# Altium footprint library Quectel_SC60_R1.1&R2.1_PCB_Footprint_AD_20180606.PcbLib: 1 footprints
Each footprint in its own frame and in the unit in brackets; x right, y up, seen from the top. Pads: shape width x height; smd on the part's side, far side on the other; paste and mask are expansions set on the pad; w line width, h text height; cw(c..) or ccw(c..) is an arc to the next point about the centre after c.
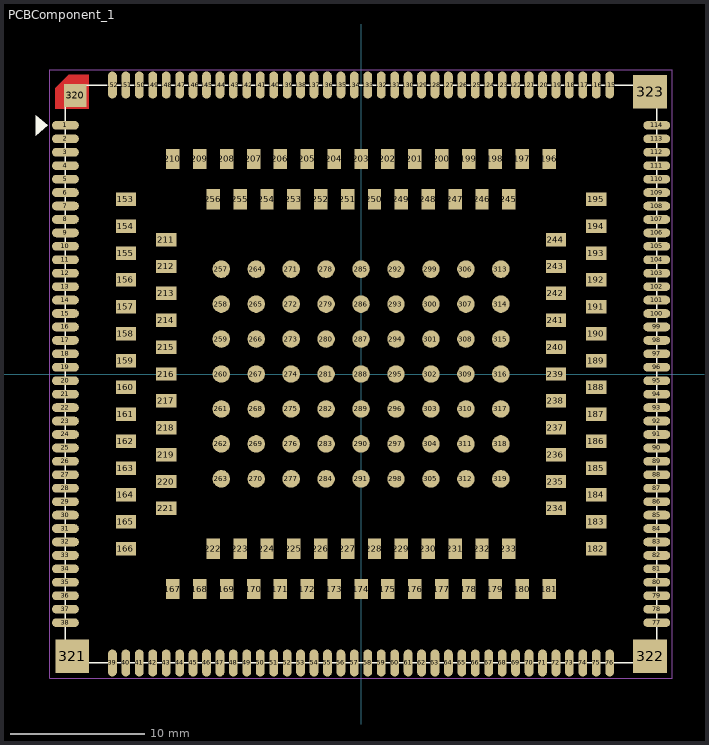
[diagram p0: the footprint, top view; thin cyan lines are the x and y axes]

## PCBComponent_1 [mm]
pads (323):
  oval 2x0.65 smd mask+0.05: 1(-22,18.5) 2(-22,17.5) 3(-22,16.5) 4(-22,15.5) 5(-22,14.5) 6(-22,13.5) 7(-22,12.5) 8(-22,11.5) 9(-22,10.5) 10(-22,9.5) 11(-22,8.5) 12(-22,7.5) 13(-22,6.5) 14(-22,5.5) 15(-22,4.5) 16(-22,3.5) 17(-22,2.5) 18(-22,1.5) 19(-22,0.5) 20(-22,-0.5) 21(-22,-1.5) 22(-22,-2.5) 23(-22,-3.5) 24(-22,-4.5) 25(-22,-5.5) 26(-22,-6.5) 27(-22,-7.5) 28(-22,-8.5) 29(-22,-9.5) 30(-22,-10.5) 31(-22,-11.5) 32(-22,-12.5) 33(-22,-13.5) 34(-22,-14.5) 35(-22,-15.5) 36(-22,-16.5) 37(-22,-17.5) 38(-22,-18.5) 77(22,-18.5) 78(22,-17.5) 79(22,-16.5) 80(22,-15.5) 81(22,-14.5) 82(22,-13.5) 83(22,-12.5) 84(22,-11.5) 85(22,-10.5) 86(22,-9.5) 87(22,-8.5) 88(22,-7.5) 89(22,-6.5) 90(22,-5.5) 91(22,-4.5) 92(22,-3.5) 93(22,-2.5) 94(22,-1.5) 95(22,-0.5) 96(22,0.5) 97(22,1.5) 98(22,2.5) 99(22,3.5) 100(22,4.5) 101(22,5.5) 102(22,6.5) 103(22,7.5) 104(22,8.5) 105(22,9.5) 106(22,10.5) 107(22,11.5) 108(22,12.5) 109(22,13.5) 110(22,14.5) 111(22,15.5) 112(22,16.5) 113(22,17.5) 114(22,18.5)
  oval 0.65x2 smd mask+0.05: 39(-18.5,-21.5) 40(-17.5,-21.5) 41(-16.5,-21.5) 42(-15.5,-21.5) 43(-14.5,-21.5) 44(-13.5,-21.5) 45(-12.5,-21.5) 46(-11.5,-21.5) 47(-10.5,-21.5) 48(-9.5,-21.5) 49(-8.5,-21.5) 50(-7.5,-21.5) 51(-6.5,-21.5) 52(-5.5,-21.5) 53(-4.5,-21.5) 54(-3.5,-21.5) 55(-2.5,-21.5) 56(-1.5,-21.5) 57(-0.5,-21.5) 58(0.5,-21.5) 59(1.5,-21.5) 60(2.5,-21.5) 61(3.5,-21.5) 62(4.5,-21.5) 63(5.5,-21.5) 64(6.5,-21.5) 65(7.5,-21.5) 66(8.5,-21.5) 67(9.5,-21.5) 68(10.5,-21.5) 69(11.5,-21.5) 70(12.5,-21.5) 71(13.5,-21.5) 72(14.5,-21.5) 73(15.5,-21.5) 74(16.5,-21.5) 75(17.5,-21.5) 76(18.5,-21.5) 115(18.5,21.5) 116(17.5,21.5) 117(16.5,21.5) 118(15.5,21.5) 119(14.5,21.5) 120(13.5,21.5) 121(12.5,21.5) 122(11.5,21.5) 123(10.5,21.5) 124(9.5,21.5) 125(8.5,21.5) 126(7.5,21.5) 127(6.5,21.5) 128(5.5,21.5) 129(4.5,21.5) 130(3.5,21.5) 131(2.5,21.5) 132(1.5,21.5) 133(0.5,21.5) 134(-0.5,21.5) 135(-1.5,21.5) 136(-2.5,21.5) 137(-3.5,21.5) 138(-4.5,21.5) 139(-5.5,21.5) 140(-6.5,21.5) 141(-7.5,21.5) 142(-8.5,21.5) 143(-9.5,21.5) 144(-10.5,21.5) 145(-11.5,21.5) 146(-12.5,21.5) 147(-13.5,21.5) 148(-14.5,21.5) 149(-15.5,21.5) 150(-16.5,21.5) 151(-17.5,21.5) 152(-18.5,21.5)
  rect 1.5x1 smd mask+0.05: 153(-17.5,13) 154(-17.5,11) 155(-17.5,9) 156(-17.5,7) 157(-17.5,5) 158(-17.5,3) 159(-17.5,1) 160(-17.5,-1) 161(-17.5,-3) 162(-17.5,-5) 163(-17.5,-7) 164(-17.5,-9) 165(-17.5,-11) 166(-17.5,-13) 182(17.5,-13) 183(17.5,-11) 184(17.5,-9) 185(17.5,-7) 186(17.5,-5) 187(17.5,-3) 188(17.5,-1) 189(17.5,1) 190(17.5,3) 191(17.5,5) 192(17.5,7) 193(17.5,9) 194(17.5,11) 195(17.5,13) 211(-14.5,10) 212(-14.5,8) 213(-14.5,6) 214(-14.5,4) 215(-14.5,2) 216(-14.5,0) 217(-14.5,-2) 218(-14.5,-4) 219(-14.5,-6) 220(-14.5,-8) 221(-14.5,-10) 234(14.5,-10) 235(14.5,-8) 236(14.5,-6) 237(14.5,-4) 238(14.5,-2) 239(14.5,0) 240(14.5,2) 241(14.5,4) 242(14.5,6) 243(14.5,8) 244(14.5,10)
  rect 1x1.5 smd mask+0.05: 167(-14,-16) 168(-12,-16) 169(-10,-16) 170(-8,-16) 171(-6,-16) 172(-4,-16) 173(-2,-16) 174(0,-16) 175(2,-16) 176(4,-16) 177(6,-16) 178(8,-16) 179(10,-16) 180(12,-16) 181(14,-16) 196(14,16) 197(12,16) 198(10,16) 199(8,16) 200(6,16) 201(4,16) 202(2,16) 203(0,16) 204(-2,16) 205(-4,16) 206(-6,16) 207(-8,16) 208(-10,16) 209(-12,16) 210(-14,16) 222(-11,-13) 223(-9,-13) 224(-7,-13) 225(-5,-13) 226(-3,-13) 227(-1,-13) 228(1,-13) 229(3,-13) 230(5,-13) 231(7,-13) 232(9,-13) 233(11,-13) 245(11,13) 246(9,13) 247(7,13) 248(5,13) 249(3,13) 250(1,13) 251(-1,13) 252(-3,13) 253(-5,13) 254(-7,13) 255(-9,13) 256(-11,13)
  round 1.3 smd mask+0.05: 257(-10.4,7.8) 258(-10.4,5.2) 259(-10.4,2.6) 260(-10.4,0) 261(-10.4,-2.6) 262(-10.4,-5.2) 263(-10.4,-7.8) 264(-7.8,7.8) 265(-7.8,5.2) 266(-7.8,2.6) 267(-7.8,0) 268(-7.8,-2.6) 269(-7.8,-5.2) 270(-7.8,-7.8) 271(-5.2,7.8) 272(-5.2,5.2) 273(-5.2,2.6) 274(-5.2,0) 275(-5.2,-2.6) 276(-5.2,-5.2) 277(-5.2,-7.8) 278(-2.6,7.8) 279(-2.6,5.2) 280(-2.6,2.6) 281(-2.6,0) 282(-2.6,-2.6) 283(-2.6,-5.2) 284(-2.6,-7.8) 285(0,7.8) 286(0,5.2) 287(0,2.6) 288(0,0) 289(0,-2.6) 290(0,-5.2) 291(0,-7.8) 292(2.6,7.8) 293(2.6,5.2) 294(2.6,2.6) 295(2.6,0) 296(2.6,-2.6) 297(2.6,-5.2) 298(2.6,-7.8) 299(5.2,7.8) 300(5.2,5.2) 301(5.2,2.6) 302(5.2,0) 303(5.2,-2.6) 304(5.2,-5.2) 305(5.2,-7.8) 306(7.8,7.8) 307(7.8,5.2) 308(7.8,2.6) 309(7.8,0) 310(7.8,-2.6) 311(7.8,-5.2) 312(7.8,-7.8) 313(10.4,7.8) 314(10.4,5.2) 315(10.4,2.6) 316(10.4,0) 317(10.4,-2.6) 318(10.4,-5.2) 319(10.4,-7.8)
  rect 1.7x1.7 smd: 320(-21.266,20.723)
  rect 2.5x2.5 smd mask+0.05: 321(-21.5,-21) 322(21.5,-21) 323(21.5,21)
Top Layer:
  region: -20.25,19.75 -20.25,22.25 -21.75,22.25 -22.75,21.25 -22.75,19.75
Top Overlay:
  region: -23.3,18.5 -24.2,19.271 -24.2,17.729
  lines w0.1: -22,-21.5 22,-21.5 22,21.5 -21,21.5 -22,20.5 -22,-21.5
Top Paste:
  region: -20.25,19.75 -20.25,22.25 -21.75,22.25 -22.75,21.25 -22.75,19.75
Top Solder:
  region: -20.2,19.7 -20.2,22.3 -21.8,22.3 -22.8,21.3 -22.8,19.7
Mechanical 1:
  lines w0.01: -23.15,-22.65 23.15,-22.65 23.15,22.65 -23.15,22.65 -23.15,-22.65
